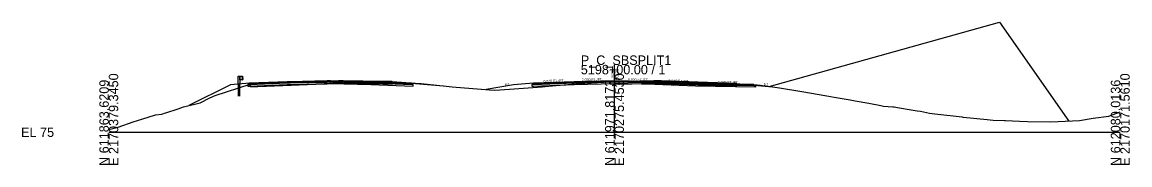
# Model space of a CAD drawing. Extents: x -26 to 1303, y -3010 to 12033.
# Drawn here: x 974.3 to 1302.8, y 990.3 to 1032.7 of the extents above; entities that cross this region are included whole.
import ezdxf

# ---------------------------------------------------------------- set-up
doc = ezdxf.new("R2010")
doc.units = 0
for name, color, linetype in [('RD_GPK_XS_Cell', 7, 'Continuous'), ('RD_PD_Final_TrvlWay', 7, 'Continuous'), ('RD_Sketch10', 7, 'Continuous'), ('RD_XS_Base', 7, 'Continuous'), ('RD_XS_ExGround', 7, 'Continuous'), ('RD_XS_ExPaveRet', 7, 'Continuous'), ('RD_XS_GR', 7, 'Continuous'), ('RD_XS_Greenside', 7, 'Continuous'), ('RD_XS_Pave', 7, 'Continuous'), ('RD_XS_PaveOvlay_CP', 7, 'Continuous'), ('RD_XS_TieSlope', 7, 'Continuous'), ('RD_XS_TX_Elev_EX', 7, 'Continuous'), ('RD_XS_TX_Elev_PR', 7, 'Continuous'), ('RD_XS_TX_Slope', 7, 'Continuous')]:
    doc.layers.add(name, color=color, linetype=linetype)

msp = doc.modelspace()

# ---------------------------------------------------------------- linework, layer by layer
at = {"layer": 'RD_GPK_XS_Cell'}
for p, q in [((1150, 1000), (1150, 1020)), ((1000, 1000), (1150, 1000)), ((1150, 1000), (1300, 1000))]:
    msp.add_line(p, q, dxfattribs=at)
at = {"layer": 'RD_PD_Final_TrvlWay'}
msp.add_lwpolyline([(1038.91, 1010.7), (1038.91, 1014.3), (1038.41, 1014.26), (1038.41, 1010.7)], dxfattribs=at)
at = {"layer": 'RD_Sketch10'}
msp.add_lwpolyline([(1195.89, 1013.59), (1264.2, 1032.71), (1284.73, 1003.33)], dxfattribs=at)
at = {"layer": 'RD_XS_Base'}
for p, q in [((1041.74, 1014.21), (1041.27, 1014.19)), ((1041.27, 1014.19), (1041.27, 1014.16)), ((1041.27, 1014.16), (1041.27, 1013.69)), ((1041.27, 1013.69), (1041.74, 1013.71)), ((1041.77, 1014.21), (1041.74, 1014.21)), ((1041.74, 1013.71), (1041.77, 1013.71)), ((1052.9, 1014.66), (1041.77, 1014.21)), ((1041.77, 1013.71), (1052.9, 1014.16)), ((1053.77, 1014.69), (1052.9, 1014.66)), ((1052.9, 1014.16), (1053.77, 1014.19)), ((1064.74, 1014.91), (1053.77, 1014.69)), ((1053.77, 1014.19), (1064.74, 1014.41)), ((1065.77, 1014.93), (1064.74, 1014.91)), ((1064.74, 1014.41), (1065.77, 1014.43)), ((1065.77, 1015.08), (1065.77, 1015.09)), ((1065.77, 1015.09), (1065.77, 1015.03)), ((1065.77, 1014.93), (1065.77, 1015.09)), ((1065.77, 1015.09), (1065.77, 1015.09)), ((1065.77, 1015.09), (1065.77, 1015.09)), ((1065.77, 1015.09), (1065.77, 1014.43)), ((1065.77, 1014.93), (1065.77, 1015.08)), ((1065.77, 1015.03), (1065.77, 1014.43)), ((1065.77, 1014.89), (1065.77, 1014.93)), ((1065.77, 1014.43), (1065.77, 1014.93)), ((1065.77, 1014.93), (1065.77, 1014.93)), ((1065.77, 1014.93), (1065.77, 1014.93)), ((1065.77, 1014.93), (1065.77, 1014.93)), ((1077.77, 1014.69), (1065.77, 1014.93)), ((1065.77, 1014.43), (1065.77, 1014.89)), ((1065.77, 1014.43), (1065.77, 1014.43)), ((1065.77, 1014.43), (1065.77, 1014.43)), ((1065.77, 1014.43), (1077.77, 1014.19)), ((1089.77, 1014.21), (1077.77, 1014.69)), ((1077.77, 1014.19), (1090.27, 1013.69)), ((1079.77, 1014.61), (1079.77, 1014.61)), ((1079.77, 1014.11), (1079.77, 1014.11)), ((1090.27, 1014.19), (1089.77, 1014.21)), ((1089.77, 1014.21), (1089.77, 1014.21)), ((1090.27, 1013.69), (1090.27, 1014.19)), ((1090.27, 1014.19), (1090.27, 1014.19)), ((1126, 1014.21), (1125.5, 1014.19)), ((1125.5, 1014.19), (1125.5, 1014.19)), ((1125.5, 1014.19), (1125.5, 1013.69)), ((1125.5, 1013.69), (1126, 1013.71)), ((1138, 1014.69), (1126, 1014.21)), ((1126, 1014.21), (1126, 1014.21)), ((1126, 1013.71), (1138, 1014.19)), ((1126, 1013.71), (1126, 1013.71)), ((1136, 1014.61), (1136, 1014.61)), ((1136, 1014.11), (1136, 1014.11)), ((1150, 1014.93), (1138, 1014.69)), ((1138, 1014.19), (1150, 1014.43)), ((1150, 1014.43), (1150, 1015.09)), ((1150, 1015.09), (1150, 1015.09)), ((1150, 1015.09), (1150, 1015.09)), ((1150, 1015.09), (1150, 1014.93)), ((1150, 1014.93), (1150, 1014.93)), ((1150, 1014.93), (1162, 1014.69)), ((1150, 1014.93), (1150, 1014.93)), ((1150, 1014.43), (1150, 1014.93)), ((1150, 1014.93), (1150, 1014.93)), ((1150, 1014.93), (1150, 1014.93)), ((1162, 1014.19), (1150, 1014.43)), ((1150, 1014.43), (1150, 1014.43)), ((1150, 1014.43), (1150, 1014.43)), ((1162, 1014.69), (1162, 1014.69)), ((1162, 1014.69), (1174, 1014.21)), ((1174, 1013.71), (1162, 1014.19)), ((1162, 1014.19), (1162, 1014.19)), ((1174, 1014.21), (1174, 1014.21)), ((1174, 1014.21), (1191.3, 1013.87)), ((1191.8, 1013.36), (1174, 1013.71)), ((1174, 1013.71), (1174, 1013.71)), ((1191.3, 1013.87), (1191.3, 1013.87)), ((1191.3, 1013.87), (1191.8, 1013.86)), ((1191.8, 1013.86), (1191.8, 1013.86)), ((1191.8, 1013.86), (1191.8, 1013.36))]:
    msp.add_line(p, q, dxfattribs=at)
at = {"layer": 'RD_XS_ExGround'}
msp.add_lwpolyline([(1000, 1000.8), (1002.75, 1001.51), (1007.25, 1003.05), (1009.8, 1003.93), (1013.87, 1005.21), (1015.7, 1005.41), (1016.04, 1005.42), (1016.5, 1005.63), (1016.92, 1005.77), (1020.56, 1006.99), (1022.16, 1007.54), (1025.96, 1008.41), (1027.08, 1008.73), (1029.97, 1010.18), (1031.54, 1010.87), (1041.98, 1014.3), (1066.88, 1015.2), (1068.35, 1015.26), (1068.81, 1015.25), (1084.01, 1015.07), (1086.86, 1014.87), (1089.36, 1014.72), (1092.63, 1014.5), (1096.39, 1014.09), (1101.84, 1013.5), (1112.96, 1012.62), (1114.54, 1012.49), (1118.89, 1012.81), (1128.51, 1013.5), (1130.44, 1013.69), (1139.62, 1014.5), (1140.07, 1014.55), (1141.17, 1014.58), (1148.76, 1015.01), (1161.67, 1015.22), (1163.81, 1015.25), (1177.61, 1014.78), (1186.13, 1014.48), (1189.26, 1014.2), (1196.88, 1013.5), (1198.93, 1013.16), (1205.57, 1012.08), (1212.92, 1010.8), (1215.14, 1010.44), (1219.89, 1009.66), (1221.38, 1009.37), (1225.46, 1008.6), (1229.03, 1007.9), (1229.78, 1007.78), (1232.54, 1007.56), (1232.72, 1007.53), (1232.9, 1007.5), (1233.96, 1007.33), (1238.55, 1006.56), (1239.16, 1006.45), (1239.75, 1006.38), (1240.73, 1006.21), (1243.41, 1005.62), (1244.96, 1005.5), (1253.07, 1004.54), (1253.32, 1004.51), (1253.39, 1004.5), (1260.53, 1003.77), (1262.3, 1003.56), (1265.71, 1003.5), (1265.97, 1003.49), (1270.14, 1003.25), (1272.51, 1003.2), (1279.41, 1003.08), (1281.6, 1003.17), (1287.86, 1003.48), (1291.99, 1004.15), (1296.61, 1004.8), (1300, 1006.07)], dxfattribs=at)
at = {"layer": 'RD_XS_ExPaveRet'}
for points in [[(1084.01, 1015.07), (1084.01, 1015.07), (1084.01, 1014.9), (1084.01, 1014.32), (1084.01, 1014.32), (1084.01, 1014.32), (1081.24, 1014.35), (1069.48, 1014.5), (1068.93, 1014.5), (1068.35, 1014.51), (1068.1, 1014.5), (1066.36, 1014.43), (1044.19, 1013.63), (1041.98, 1013.55), (1041.98, 1013.55), (1041.98, 1013.55), (1041.98, 1013.65), (1041.98, 1014.3), (1041.98, 1014.3), (1041.98, 1014.3), (1044.19, 1014.38), (1066.36, 1015.18), (1068.1, 1015.25), (1068.35, 1015.26), (1068.93, 1015.25), (1069.48, 1015.25), (1081.24, 1015.1), (1084.01, 1015.07), (1084.01, 1015.07)], [(1081.24, 1015.1), (1069.48, 1015.25), (1068.93, 1015.25), (1068.35, 1015.26), (1068.1, 1015.25), (1066.36, 1015.18), (1044.19, 1014.38), (1041.98, 1014.3), (1041.98, 1014.3), (1041.98, 1013.65), (1041.98, 1013.55), (1041.98, 1013.55), (1044.19, 1013.63), (1066.36, 1014.43), (1068.1, 1014.5), (1068.35, 1014.51), (1068.93, 1014.5), (1069.48, 1014.5), (1081.24, 1014.35), (1084.01, 1014.32)], [(1177.61, 1014.78), (1163.81, 1015.25), (1163.81, 1015.25), (1161.67, 1015.22), (1161.67, 1015.22), (1148.76, 1015.01), (1148.76, 1015.01), (1148.76, 1014.26), (1148.76, 1014.26), (1148.76, 1014.26), (1161.67, 1014.47), (1161.67, 1014.47), (1163.81, 1014.5), (1163.81, 1014.5), (1177.61, 1014.03), (1177.61, 1014.03), (1186.13, 1013.73), (1186.13, 1014.48), (1186.13, 1014.48), (1177.61, 1014.78), (1177.61, 1014.78)], [(1177.61, 1014.78), (1163.81, 1015.25), (1161.67, 1015.22), (1148.76, 1015.01), (1148.76, 1014.26), (1161.67, 1014.47), (1163.81, 1014.5), (1177.61, 1014.03), (1186.13, 1013.73), (1186.13, 1014.48), (1177.61, 1014.78)], [(1084.01, 1014.32), (1084.01, 1014.9), (1084.01, 1015.07), (1084.01, 1015.07), (1081.24, 1015.1)], [(1084.01, 1014.32), (1084.01, 1014.32)]]:
    msp.add_lwpolyline(points, dxfattribs=at)
at = {"layer": 'RD_XS_GR'}
for p, q in [((1038.41, 1014.26), (1038.41, 1016.7)), ((1038.41, 1016.7), (1038.66, 1016.7)), ((1038.66, 1016.7), (1038.91, 1016.7)), ((1038.91, 1016.7), (1038.91, 1014.3)), ((1038.91, 1015.53), (1038.91, 1016.7)), ((1038.91, 1016.7), (1039.58, 1016.7)), ((1039.58, 1015.53), (1038.91, 1015.53)), ((1039.58, 1016.7), (1039.58, 1015.53)), ((1039.59, 1016.68), (1039.58, 1016.7)), ((1039.58, 1016.7), (1039.58, 1016.63)), ((1039.58, 1016.63), (1039.58, 1015.53)), ((1039.58, 1016.11), (1039.83, 1016.39)), ((1039.59, 1016.1), (1039.58, 1016.11)), ((1039.58, 1015.53), (1039.83, 1015.8)), ((1039.85, 1016.4), (1039.59, 1016.68)), ((1039.85, 1015.82), (1039.59, 1016.1)), ((1039.83, 1016.39), (1039.85, 1016.4)), ((1039.83, 1015.8), (1039.85, 1015.82)), ((1038.91, 1014.3), (1038.41, 1014.26))]:
    msp.add_line(p, q, dxfattribs=at)
at = {"layer": 'RD_XS_Greenside'}
for p, q in [((1036.1, 1014.08), (1023.77, 1007.91)), ((1120, 1014.05), (1111.91, 1012.7)), ((1193.3, 1014.02), (1195.89, 1013.59))]:
    msp.add_line(p, q, dxfattribs=at)
at = {"layer": 'RD_XS_Pave'}
for p, q in [((1064.74, 1015.23), (1053.77, 1015.01)), ((1065.77, 1015.25), (1064.74, 1015.23)), ((1077.77, 1015.01), (1065.77, 1015.25)), ((1065.77, 1015.25), (1065.77, 1015.25)), ((1065.77, 1015.25), (1065.77, 1015.25)), ((1150, 1015.25), (1138, 1015.01)), ((1162, 1015.01), (1150, 1015.25)), ((1150, 1015.25), (1150, 1015.25)), ((1150, 1015.25), (1150, 1015.25)), ((1052.9, 1014.98), (1041.77, 1014.53)), ((1052.9, 1014.82), (1041.77, 1014.37)), ((1041.77, 1014.37), (1052.9, 1014.82)), ((1041.77, 1014.21), (1052.9, 1014.66)), ((1041.77, 1014.53), (1041.77, 1014.52)), ((1041.77, 1014.52), (1041.77, 1014.37)), ((1041.77, 1014.37), (1041.77, 1014.36)), ((1041.77, 1014.36), (1041.77, 1014.21)), ((1053.77, 1015.01), (1052.9, 1014.98)), ((1053.77, 1014.85), (1052.9, 1014.82)), ((1052.9, 1014.82), (1053.77, 1014.85)), ((1052.9, 1014.66), (1053.77, 1014.69)), ((1064.74, 1015.07), (1053.77, 1014.85)), ((1053.77, 1014.85), (1064.74, 1015.07)), ((1053.77, 1014.69), (1064.74, 1014.91)), ((1065.77, 1015.09), (1064.74, 1015.07)), ((1064.74, 1015.07), (1065.77, 1015.09)), ((1064.74, 1014.91), (1065.77, 1014.93)), ((1065.77, 1015.08), (1065.77, 1015.09)), ((1065.77, 1015.09), (1065.77, 1015.08)), ((1065.77, 1014.93), (1065.77, 1015.09)), ((1065.77, 1015.09), (1065.77, 1015.09)), ((1065.77, 1015.09), (1065.77, 1015.09)), ((1065.77, 1015.09), (1065.77, 1015.09)), ((1065.77, 1015.09), (1065.77, 1015.09)), ((1065.77, 1015.09), (1077.77, 1014.85)), ((1077.77, 1014.85), (1065.77, 1015.09)), ((1065.77, 1015.09), (1065.77, 1015.09)), ((1065.77, 1015.09), (1065.77, 1015.09)), ((1065.77, 1015.09), (1065.77, 1014.93)), ((1065.77, 1014.93), (1065.77, 1015.08)), ((1065.77, 1015.08), (1065.77, 1014.93)), ((1065.77, 1014.93), (1065.77, 1014.93)), ((1065.77, 1014.93), (1065.77, 1014.93)), ((1065.77, 1014.93), (1077.77, 1014.69)), ((1089.77, 1014.53), (1077.77, 1015.01)), ((1077.77, 1014.85), (1089.77, 1014.37)), ((1089.77, 1014.37), (1077.77, 1014.85)), ((1077.77, 1014.69), (1089.77, 1014.21)), ((1079.77, 1014.93), (1079.77, 1014.93)), ((1079.77, 1014.77), (1079.77, 1014.77)), ((1079.77, 1014.77), (1079.77, 1014.77)), ((1079.77, 1014.61), (1079.77, 1014.61)), ((1089.77, 1014.37), (1089.77, 1014.53)), ((1089.77, 1014.53), (1089.77, 1014.53)), ((1089.77, 1014.21), (1089.77, 1014.37)), ((1089.77, 1014.37), (1089.77, 1014.37)), ((1138, 1015.01), (1126, 1014.53)), ((1138, 1014.85), (1126, 1014.37)), ((1126, 1014.37), (1138, 1014.85)), ((1126, 1014.21), (1138, 1014.69)), ((1126, 1014.53), (1126, 1014.53)), ((1126, 1014.53), (1126, 1014.37)), ((1126, 1014.37), (1126, 1014.37)), ((1126, 1014.37), (1126, 1014.21)), ((1136, 1014.93), (1136, 1014.93)), ((1136, 1014.77), (1136, 1014.77)), ((1136, 1014.77), (1136, 1014.77)), ((1136, 1014.61), (1136, 1014.61)), ((1150, 1015.09), (1138, 1014.85)), ((1138, 1014.85), (1150, 1015.09)), ((1138, 1014.69), (1150, 1014.93)), ((1150, 1014.93), (1150, 1015.09)), ((1150, 1015.09), (1150, 1015.09)), ((1150, 1015.09), (1150, 1015.09)), ((1150, 1015.09), (1150, 1015.09)), ((1150, 1015.09), (1150, 1015.09)), ((1150, 1015.09), (1162, 1014.85)), ((1162, 1014.85), (1150, 1015.09)), ((1150, 1015.09), (1150, 1015.09)), ((1150, 1015.09), (1150, 1015.09)), ((1150, 1015.09), (1150, 1015.09)), ((1150, 1015.09), (1150, 1014.93)), ((1150, 1014.93), (1150, 1014.93)), ((1150, 1014.93), (1150, 1014.93)), ((1150, 1014.93), (1150, 1014.93)), ((1150, 1014.93), (1162, 1014.69)), ((1174, 1014.53), (1162, 1015.01)), ((1162, 1015.01), (1162, 1015.01)), ((1162, 1014.85), (1162, 1014.85)), ((1162, 1014.85), (1174, 1014.37)), ((1174, 1014.37), (1162, 1014.85)), ((1162, 1014.85), (1162, 1014.85)), ((1162, 1014.69), (1162, 1014.69)), ((1162, 1014.69), (1174, 1014.21)), ((1191.3, 1014.18), (1174, 1014.53)), ((1174, 1014.53), (1174, 1014.53)), ((1174, 1014.37), (1174, 1014.37)), ((1174, 1014.37), (1191.3, 1014.02)), ((1191.3, 1014.02), (1174, 1014.37)), ((1174, 1014.37), (1174, 1014.37)), ((1174, 1014.21), (1191.3, 1013.87)), ((1174, 1014.21), (1174, 1014.21)), ((1191.3, 1014.02), (1191.3, 1014.18)), ((1191.3, 1014.18), (1191.3, 1014.18)), ((1191.3, 1013.87), (1191.3, 1014.02)), ((1191.3, 1014.02), (1191.3, 1014.02))]:
    msp.add_line(p, q, dxfattribs=at)
at = {"layer": 'RD_XS_PaveOvlay_CP'}
for p, q in [((1053.77, 1015.01), (1065.77, 1015.25)), ((1065.77, 1015.25), (1077.77, 1015.01)), ((1150, 1015.25), (1138, 1015.01)), ((1162, 1015.01), (1150, 1015.25)), ((1150, 1015.25), (1150, 1015.25)), ((1150, 1015.25), (1150, 1015.25)), ((1041.77, 1014.53), (1053.77, 1015.01)), ((1077.77, 1015.01), (1089.77, 1014.53)), ((1138, 1015.01), (1126, 1014.53)), ((1136, 1014.93), (1136, 1014.93)), ((1174, 1014.53), (1162, 1015.01)), ((1162, 1015.01), (1162, 1015.01)), ((1191.3, 1014.18), (1174, 1014.53)), ((1174, 1014.53), (1174, 1014.53))]:
    msp.add_line(p, q, dxfattribs=at)
at = {"layer": 'RD_XS_TieSlope'}
for p, q in [((1041.77, 1014.53), (1036.1, 1014.08)), ((1089.77, 1014.53), (1099.28, 1013.77)), ((1126, 1014.53), (1120, 1014.05)), ((1191.3, 1014.18), (1193.3, 1014.02))]:
    msp.add_line(p, q, dxfattribs=at)

# ---------------------------------------------------------------- texts
at = {"layer": 'RD_GPK_XS_Cell'}
for s, p in [('P_C_SBSPLIT1', (1140, 1020)), ('5198+00.00 / 1', (1140, 1017.2)), ('EL 75', (974, 998.6))]:
    msp.add_text(s, height=2.8, dxfattribs=at).set_placement(p)
for s, p in [('N 611863.6209', (1000, 990)), ('E 2170379.3450', (1002.8, 990)), ('N 611971.8173', (1150, 990)), ('E 2170275.4530', (1152.8, 990)), ('N 612080.0136', (1300, 990)), ('E 2170171.5610', (1302.8, 990))]:
    msp.add_text(s, height=2.8, rotation=90, dxfattribs=at).set_placement(p)
at = {"layer": 'RD_XS_TX_Elev_EX'}
msp.add_text('90.03', height=0.6, rotation=90, dxfattribs=at).set_placement((1149.66, 1016.24))
at = {"layer": 'RD_XS_TX_Elev_PR'}
msp.add_text('90.25', height=1, rotation=90, dxfattribs=at).set_placement((1151.2, 1015.47))
at = {"layer": 'RD_XS_TX_Slope'}
for s, rotation, p in [('0.040 FT./FT.', 2.2906, (1128.93, 1014.75)), ('0.020 FT./FT.', 1.1458, (1140.27, 1015.22)), ('0.020 FT./FT.', 358.8542, (1153.94, 1015.27)), ('0.040 FT./FT.', 357.7094, (1165.94, 1014.95)), ('0.020 FT./FT.', 358.8542, (1180.59, 1014.5)), ('6:1', 9.4642, (1117.56, 1013.7)), ('6:1', 350.5358, (1194.2, 1013.97))]:
    msp.add_text(s, height=0.75, rotation=rotation, dxfattribs=at).set_placement(p)

doc.saveas('drawing.dxf')
